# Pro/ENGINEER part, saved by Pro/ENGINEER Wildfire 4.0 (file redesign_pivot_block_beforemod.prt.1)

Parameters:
  METRIC = "NO"

Other parameters: PITCH, DRILL_POINT_ANGLE, DRILL_DEPTH, DRILL_DIAMETER, THREAD_DIAMETER, THREADS_PER_INCH, THREAD_DEPTH, THREAD_LENGTH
